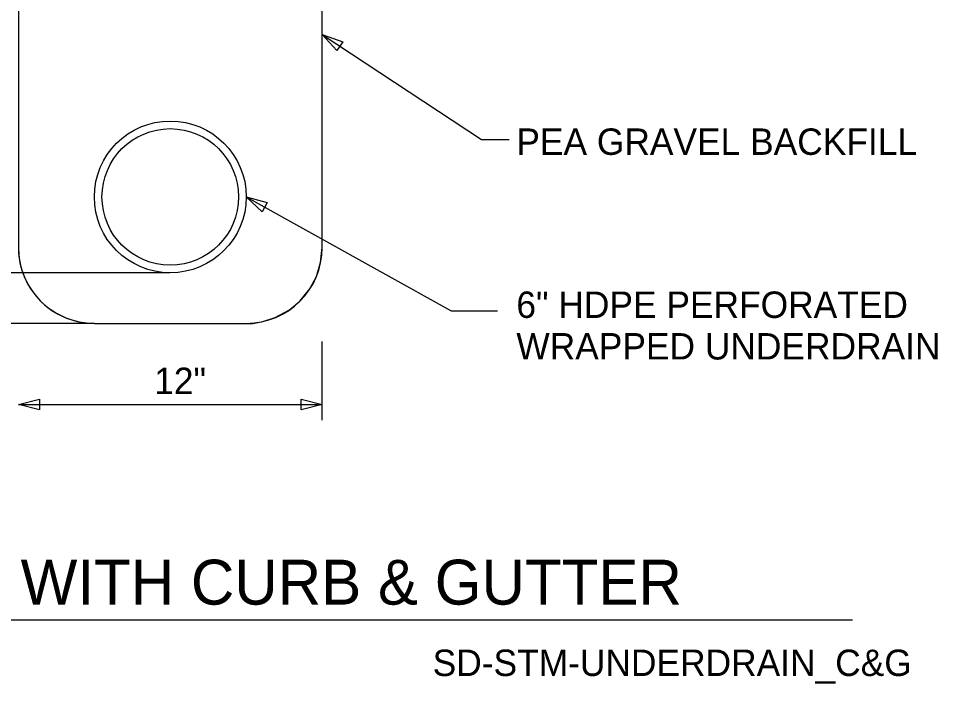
# Model space of a CAD drawing. Extents: x 10368.3 to 10426.8, y 9886.2 to 9938.1.
# Drawn here: x 10390.52 to 10426.83, y 9886.23 to 9912.53 of the extents above; entities that cross this region are included whole.
import ezdxf

# ---------------------------------------------------------------- set-up
doc = ezdxf.new("R2010")
doc.units = 0
for name, color, linetype in [('Default', 7, 'Continuous'), ('G-ANNO-TEXT', 7, 'Continuous'), ('G-ANNO-TTXT', 7, 'Continuous'), ('G-DETL-OTLN', 7, 'Continuous'), ('G-DETL-PATT', 7, 'Continuous')]:
    doc.layers.add(name, color=color, linetype=linetype)

# ---------------------------------------------------------------- blocks, each defined once
blk = doc.blocks.new('TERARR')
at = {"layer": 'Default'}
blk.add_lwpolyline([(-0.667, 0.167), (0, 0), (-0.667, -0.167)], close=True, dxfattribs=at)

msp = doc.modelspace()

# ---------------------------------------------------------------- linework, layer by layer
at = {"layer": 'G-ANNO-TEXT'}
for p, q in [((10396.518, 9902.473), (10386.201, 9902.473)), ((10393.518, 9900.473), (10388.709, 9900.473)), ((10402.518, 9896.649), (10402.518, 9899.762)), ((10390.518, 9897.266), (10402.518, 9897.266)), ((10370.168, 9888.748), (10423.466, 9888.748))]:
    msp.add_line(p, q, dxfattribs=at)
for points in [[(10402.519, 9911.889), (10408.812, 9907.74), (10409.904, 9907.74)], [(10399.518, 9905.473), (10407.611, 9900.969), (10409.439, 9900.969)]]:
    msp.add_lwpolyline(points, dxfattribs=at)
at = {"layer": 'G-DETL-OTLN'}
for p, q in [((10402.518, 9903.473), (10402.518, 9917.722)), ((10393.518, 9900.473), (10399.518, 9900.473))]:
    msp.add_line(p, q, dxfattribs=at)
for radius in [3, 2.698]:
    msp.add_circle((10396.518, 9905.473), radius, dxfattribs=at)
for centre, start, end in [((10393.518, 9903.473), 180, 270), ((10399.518, 9903.473), 270, 360)]:
    msp.add_arc(centre, 3, start, end, dxfattribs=at)
at = {"layer": 'G-DETL-PATT'}
for points in [[(10390.518, 9903.473), (10390.526, 9903.251), (10390.549, 9903.035), (10390.614, 9902.708), (10390.672, 9902.538), (10390.746, 9902.325), (10390.837, 9902.124), (10390.988, 9901.861), (10391.167, 9901.613), (10391.397, 9901.352), (10391.547, 9901.211), (10391.735, 9901.059), (10392.028, 9900.871), (10392.37, 9900.701), (10392.419, 9900.677), (10392.835, 9900.552), (10393.151, 9900.497), (10393.518, 9900.473), (10399.518, 9900.473), (10399.778, 9900.472), (10400.177, 9900.543), (10400.666, 9900.701), (10401.221, 9901.008), (10401.639, 9901.352), (10402.025, 9901.839), (10402.29, 9902.325), (10402.452, 9902.878), (10402.518, 9903.473), (10402.518, 9917.721)], [(10390.518, 9917.47), (10390.518, 9903.473)]]:
    msp.add_lwpolyline(points, dxfattribs=at)
msp.add_circle((10396.518, 9905.473), 3, dxfattribs=at)

# ---------------------------------------------------------------- block references
at = {"layer": 'G-ANNO-TEXT'}
for p, xscale, yscale, rotation in [((10402.519, 9911.889), 1.2499199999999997, 1.2499200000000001, 146.60008904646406), ((10399.518, 9905.473), 1.2499200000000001, 1.2499200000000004, 150.90219371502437), ((10390.518, 9897.266), 1.24992, 1.24992, 180)]:
    msp.add_blockref('TERARR', p, dxfattribs=dict(at, xscale=xscale, yscale=yscale, rotation=rotation))
at = {"layer": 'G-ANNO-TEXT', "xscale": 1.24992, "yscale": 1.24992}
msp.add_blockref('TERARR', (10402.518, 9897.266), dxfattribs=at)

# ---------------------------------------------------------------- texts
at = {"layer": 'G-ANNO-TEXT'}
for s, p in [('PEA GRAVEL BACKFILL', (10410.187, 9907.135)), ('6" HDPE PERFORATED ', (10410.187, 9900.689)), ('WRAPPED UNDERDRAIN', (10410.187, 9899.045)), ('12"', (10395.882, 9897.679)), ('SD-STM-UNDERDRAIN_C&G', (10406.882, 9886.532))]:
    msp.add_text(s, height=1.044, dxfattribs=at).set_placement(p)
at = {"layer": 'G-ANNO-TTXT'}
msp.add_text('UNDERDRAIN WITH CURB & GUTTER', height=1.776, dxfattribs=at).set_placement((10374.112, 9889.354))

doc.saveas('drawing.dxf')
